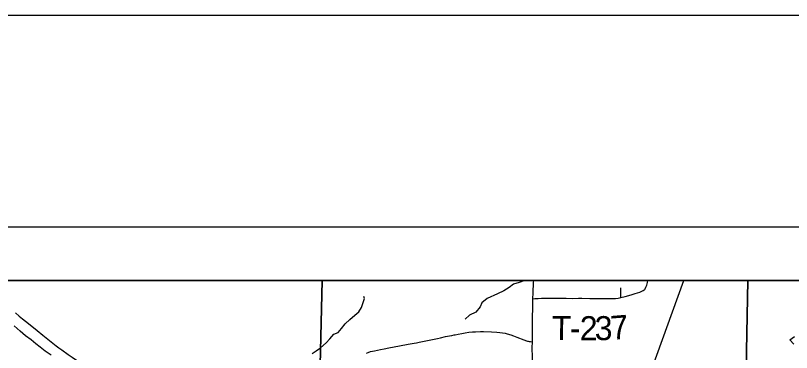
# Model space of a CAD drawing. Extents: x 0 to 34, y 0 to 22.
# Drawn here: x 5.129 to 6.964, y 21.203 to 22 of the extents above; entities that cross this region are included whole.
import ezdxf

# ---------------------------------------------------------------- set-up
doc = ezdxf.new("R2010")
doc.units = 0
for name, color, linetype in [('GM_X_Corporation', 7, 'Continuous'), ('GM_X_Major_River', 7, 'Continuous'), ('GM_X_Minor_River', 7, 'Continuous'), ('GM_X_Rail_Line', 7, 'Continuous'), ('GM_X_State_Route', 7, 'Continuous'), ('GM_X_Township_Road', 7, 'Continuous'), ('GM_X_Township_Road_Text', 7, 'Continuous'), ('SH_Border', 7, 'Continuous'), ('SH_Cut_Line', 7, 'Continuous'), ('SH_Text', 7, 'Continuous')]:
    doc.layers.add(name, color=color, linetype=linetype)

msp = doc.modelspace()

# ---------------------------------------------------------------- linework, layer by layer
at = {"layer": 'GM_X_Corporation'}
for points in [[(4.7823, 18.128), (4.7905, 18.3604), (4.8074, 19.5455), (4.8169, 20.042), (4.8194, 20.1261), (5.11, 20.116), (6.0551, 20.0845), (6.4901, 20.0752), (6.7204, 20.0659), (7.3691, 20.0515), (7.3901, 20.051), (7.814, 20.0425), (8.4311, 20.028), (8.4311, 21.3734), (1.6311, 21.3734)], [(4.0508, 18.1454), (4.7823, 18.128), (4.7905, 18.3604), (4.8074, 19.5455), (4.8169, 20.042), (4.8194, 20.1261), (5.11, 20.116), (6.0551, 20.0845), (6.4901, 20.0752), (6.7204, 20.0659), (7.3691, 20.0515), (7.3901, 20.051), (7.814, 20.0425), (8.4311, 20.028), (8.4311, 21.3734), (2.7987, 21.3734)]]:
    msp.add_lwpolyline(points, dxfattribs=at)
for points in [[(5.8536, 21.3734), (4.8467, 21.3734), (4.8451, 21.1681), (4.8435, 21.134), (5.8473, 21.1062)], [(6.8607, 21.3734), (5.8536, 21.3734), (5.8473, 21.1062), (6.8544, 21.0806)], [(7.88, 21.3734), (6.8607, 21.3734), (6.8544, 21.0806), (7.8729, 21.0548)]]:
    msp.add_lwpolyline(points, close=True, dxfattribs=at)
at = {"layer": 'GM_X_Major_River'}
msp.add_lwpolyline([(6.9694, 21.2228), (6.9599, 21.2326), (6.9704, 21.2406)], dxfattribs=at)
at = {"layer": 'GM_X_Minor_River'}
for points in [[(6.333, 21.3734), (6.333, 21.3734), (6.3198, 21.3683), (6.3059, 21.3644), (6.2961, 21.3563), (6.2833, 21.3486), (6.2686, 21.3416), (6.2442, 21.3308), (6.2314, 21.32), (6.2277, 21.3105), (6.2176, 21.2979), (6.2022, 21.2913), (6.1917, 21.2817), (6.1928, 21.2821)], [(5.8302, 21.2006), (5.84, 21.2068), (5.8502, 21.2141), (5.8637, 21.2256), (5.8723, 21.2352), (5.8816, 21.2462), (5.8914, 21.2501), (5.9, 21.2597), (5.9083, 21.2708), (5.9191, 21.2804), (5.9308, 21.2907), (5.9409, 21.2992), (5.9469, 21.3095), (5.9498, 21.319), (5.9539, 21.3304), (5.9527, 21.3349)], [(5.213, 21.1967), (5.1993, 21.206), (5.1871, 21.2154), (5.1768, 21.2236), (5.1658, 21.2326), (5.1525, 21.2423), (5.1399, 21.2535), (5.1258, 21.2659)]]:
    msp.add_lwpolyline(points, dxfattribs=at)
at = {"layer": 'GM_X_Rail_Line'}
msp.add_line((6.5871, 21.0378), (6.7091, 21.3734), dxfattribs=at)
at = {"layer": 'GM_X_State_Route'}
for points in [[(6.3523, 21.33), (6.3528, 21.3435), (6.3539, 21.3683), (6.3542, 21.3734)], [(6.3509, 21.2281), (6.351, 21.2486), (6.3511, 21.2808), (6.3519, 21.3129), (6.3523, 21.33)], [(6.319, 20.7542), (6.3193, 20.7561), (6.3287, 20.8081), (6.3387, 20.8663), (6.3441, 20.8994), (6.3462, 20.9147), (6.3479, 20.9308), (6.349, 20.945), (6.35, 20.9642), (6.3506, 20.9859), (6.3508, 21.0095), (6.3509, 21.0536), (6.351, 21.1058), (6.3509, 21.1331), (6.3511, 21.1723), (6.351, 21.1915), (6.3508, 21.2139), (6.3509, 21.2281)]]:
    msp.add_lwpolyline(points, dxfattribs=at)
at = {"layer": 'GM_X_Township_Road'}
for points in [[(6.5601, 21.3325), (6.5704, 21.3349), (6.5842, 21.3388), (6.5936, 21.342), (6.6047, 21.3458), (6.6095, 21.3475), (6.6129, 21.3492), (6.615, 21.3507), (6.6165, 21.3521), (6.6176, 21.3537), (6.6194, 21.3571), (6.6212, 21.3618), (6.6229, 21.3685), (6.6238, 21.3734)], [(6.5601, 21.3325), (6.56, 21.3361), (6.5599, 21.3416), (6.5599, 21.3478), (6.5598, 21.3544), (6.5599, 21.3561)], [(6.3509, 21.2281), (6.351, 21.2486), (6.3511, 21.2808), (6.3519, 21.3129), (6.3523, 21.33)], [(6.3523, 21.33), (6.357, 21.3302), (6.3648, 21.3306), (6.3722, 21.3311), (6.3845, 21.3311), (6.3994, 21.331), (6.4087, 21.3309), (6.4305, 21.3309), (6.4466, 21.3308), (6.4596, 21.3309), (6.4676, 21.331), (6.4868, 21.3308), (6.5011, 21.3307), (6.5092, 21.3306), (6.5259, 21.3304), (6.5384, 21.3305), (6.5471, 21.3308), (6.5539, 21.3314), (6.5601, 21.3325)], [(5.1288, 21.2967), (5.1376, 21.2889), (5.1458, 21.2822), (5.1599, 21.271), (5.1798, 21.2551), (5.1932, 21.244), (5.2053, 21.2343), (5.2254, 21.2187), (5.2315, 21.214), (5.2382, 21.209), (5.2534, 21.1983), (5.2632, 21.1917), (5.2899, 21.1735), (5.3043, 21.1639), (5.3081, 21.1611), (5.3113, 21.1587), (5.318, 21.1532), (5.3254, 21.1465), (5.3317, 21.1404), (5.3404, 21.1308), (5.3428, 21.1284), (5.3445, 21.1271), (5.3461, 21.126), (5.3475, 21.1253)], [(5.9589, 21.2015), (5.9623, 21.2029), (5.9682, 21.2048), (5.9773, 21.207), (5.9846, 21.2085), (5.9919, 21.21), (6.0004, 21.2116), (6.0114, 21.2138), (6.0364, 21.2185), (6.0571, 21.2224), (6.0711, 21.2247), (6.0772, 21.2257), (6.0833, 21.2268), (6.1028, 21.2308), (6.1106, 21.2326), (6.1263, 21.2361), (6.1333, 21.2376), (6.1458, 21.2403), (6.1548, 21.2419), (6.1608, 21.2433), (6.1657, 21.2443), (6.1681, 21.2449), (6.1754, 21.2463), (6.1838, 21.2479), (6.1922, 21.2494), (6.2006, 21.2506), (6.2091, 21.2514), (6.2125, 21.2516), (6.2164, 21.2518), (6.228, 21.2523), (6.2354, 21.2524), (6.2546, 21.2519), (6.267, 21.2512), (6.2738, 21.2504), (6.2806, 21.2494), (6.2865, 21.2482), (6.2917, 21.2469), (6.2998, 21.2445), (6.3063, 21.2423), (6.3144, 21.2392), (6.3305, 21.2325), (6.3369, 21.2303), (6.3391, 21.2297), (6.3411, 21.2292), (6.343, 21.2288), (6.3448, 21.2286), (6.3466, 21.2284), (6.3509, 21.2281)]]:
    msp.add_lwpolyline(points, dxfattribs=at)
at = {"layer": 'SH_Border'}
msp.add_lwpolyline([(1.5, 21.5), (33.5, 21.5), (33.5, 0.5), (1.5, 0.5)], close=True, dxfattribs=at)
at = {"layer": 'SH_Cut_Line'}
msp.add_lwpolyline([(0, 0), (34, 0), (34, 22), (0, 22)], close=True, dxfattribs=at)
at = {"layer": 'SH_Text'}
msp.add_line((1.6311, 21.3734), (8.4311, 21.373), dxfattribs=at)

# ---------------------------------------------------------------- texts
at = {"layer": 'GM_X_Township_Road_Text'}
for s, rotation, p in [('T', 359.6743, (6.3968, 21.2323)), ('2', 359.8255, (6.4628, 21.2319)), ('3', 0.3059, (6.4983, 21.2318)), ('7', 4.6485, (6.538, 21.2322)), ('-', 359.7017, (6.4393, 21.2321))]:
    msp.add_text(s, height=0.0568, rotation=rotation, dxfattribs=at).set_placement(p)

doc.saveas('drawing.dxf')
